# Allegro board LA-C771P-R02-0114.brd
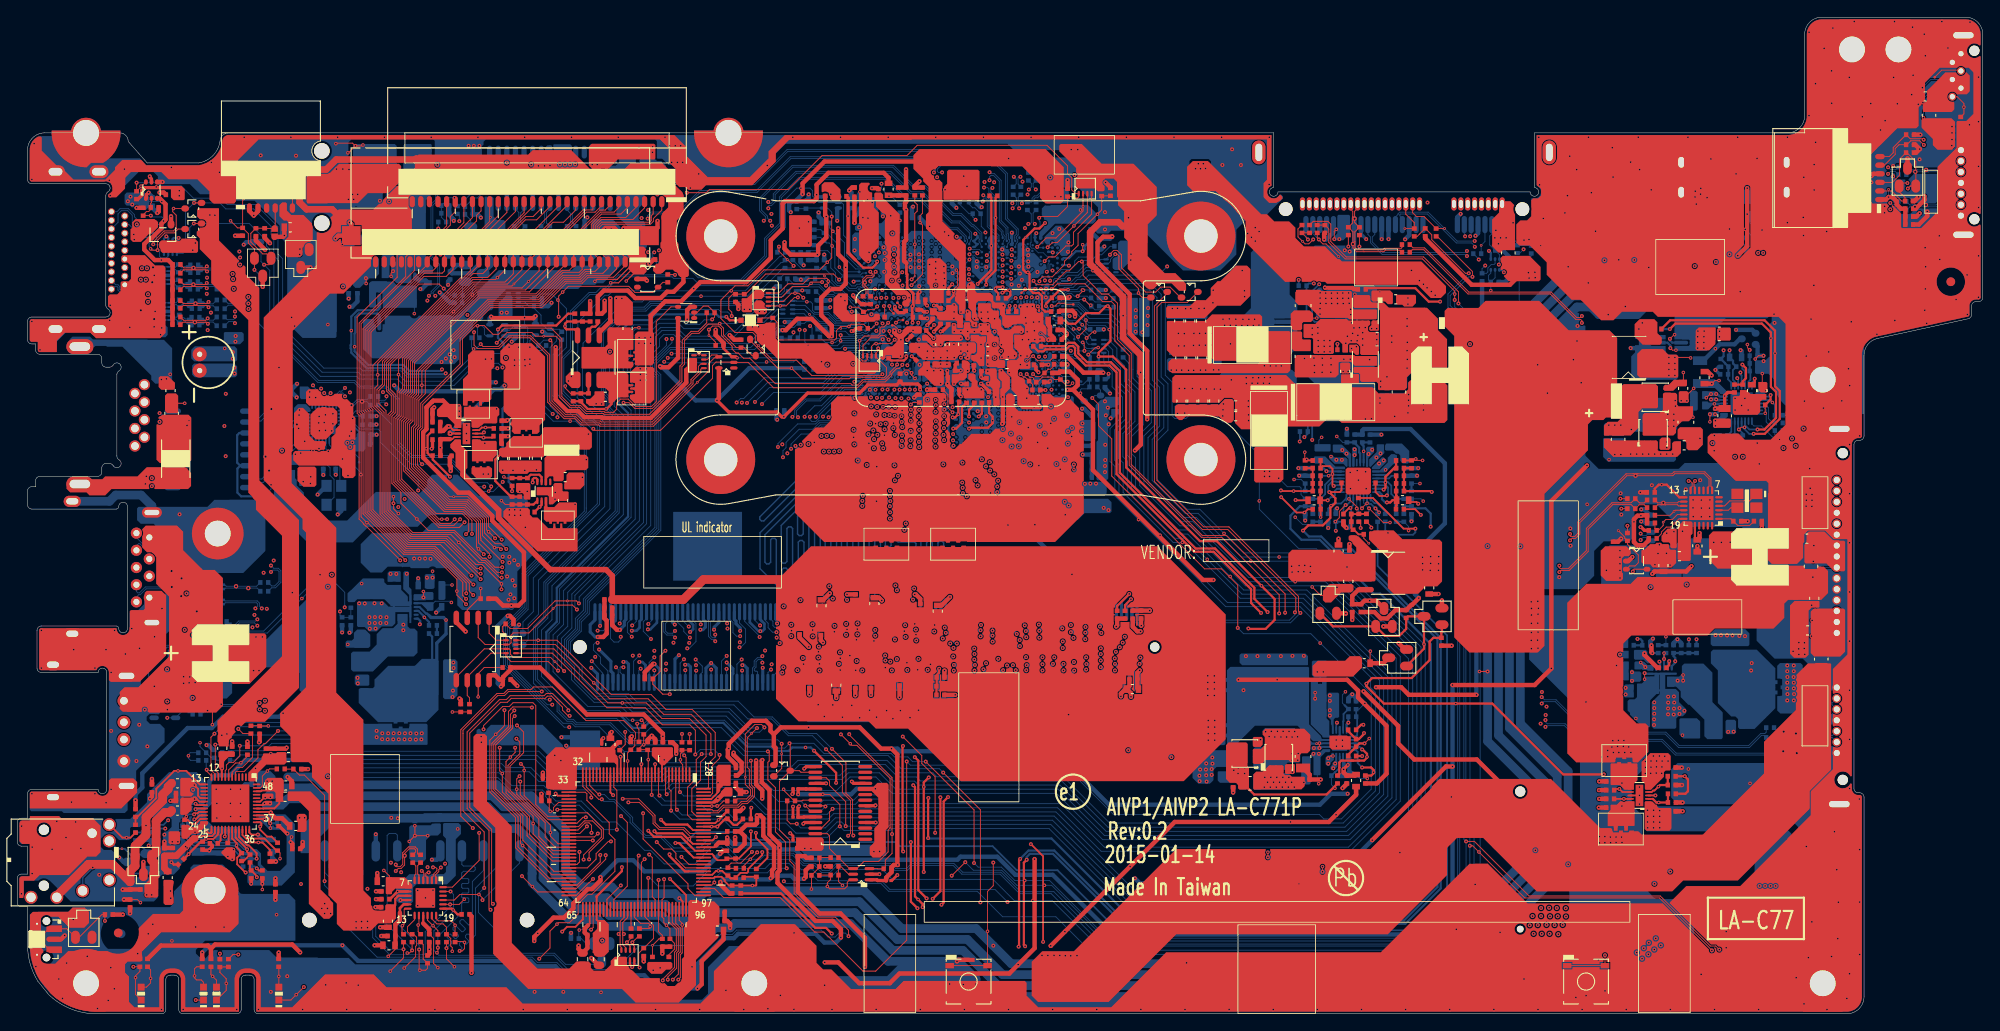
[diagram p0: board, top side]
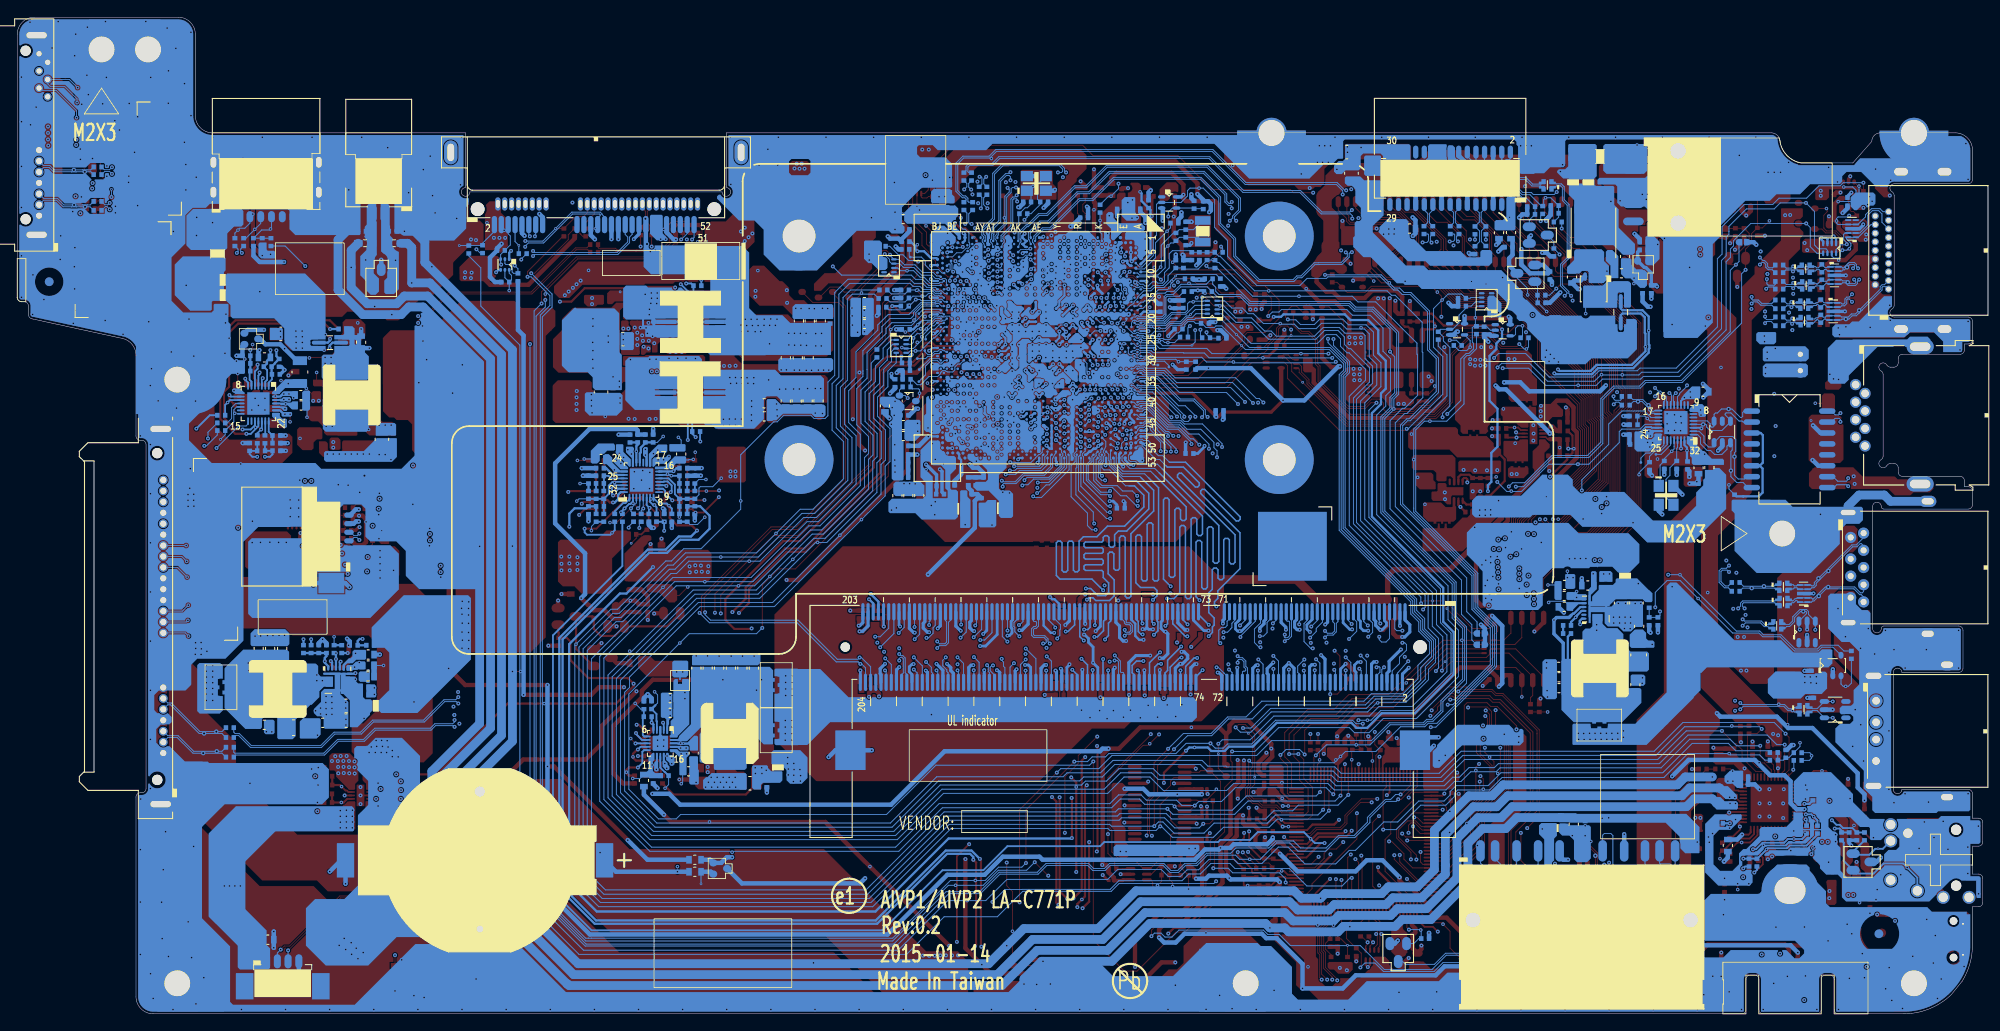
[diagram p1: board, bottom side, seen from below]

Outline 228.4 x 115.9 mm; copper layers: TOP, VCC, IN1, IN2, GND, BOTTOM. Coordinates in mm from the lower left corner of the outline.
Outline path: 0,22.25 arc(0.15,22.6) 0.5,22.75 1.2,22.75 1.2,25.6 arc(1.35,25.95) 1.7,26.1 9.4,26.1 arc(9.9,25.6) 10.4,26.1 10.4,39.7 arc(9.9,40.2) 9.4,39.7 2.8,39.7 arc(2.45,39.85) 2.3,40.2 2.3,44.6 arc(2.45,44.95) 2.8,45.1 11.5,45.1 arc(11.71,45.01) 11.8,44.8 arc(12.3,44.3) 12.8,44.8 12.8,59 arc(12.3,59.5) 11.8,59 arc(11.71,58.79) 11.5,58.7 1.7,58.7 arc(1.35,58.85) 1.2,59.2 1.2,60.8 arc(1.35,61.15) 1.7,61.3 2.14,61.3 2.14,62 arc(2.29,62.35) 2.64,62.5 9.33,62.5 arc(9.68,62.65) 9.83,63 9.83,63.5 arc(9.98,63.85) 10.33,64 10.71,64 arc(10.96,63.93) 11.15,63.75 arc(11.93,63.65) 11.83,64.43 arc(11.65,64.62) 11.58,64.87 11.58,74.33 arc(11.65,74.58) 11.83,74.77 arc(11.93,75.55) 11.15,75.45 arc(10.96,75.27) 10.71,75.2 10.33,75.2 arc(9.98,75.35) 9.83,75.7 9.83,76.2 arc(9.68,76.55) 9.33,76.7 2.64,76.7 arc(2.29,76.85) 2.14,77.2 2.14,77.9 1.7,77.9 arc(1.35,78.05) 1.2,78.4 1.2,80.53 arc(1.35,80.88) 1.7,81.03 10.3,81.03 arc(10.78,81.4) 10.55,81.96 arc(10.36,82.15) 10.3,82.4 10.3,95.16 arc(10.36,95.41) 10.55,95.6 arc(10.78,96.16) 10.3,96.53 1.7,96.53 arc(1.35,96.68) 1.2,97.03 1.2,100.45 arc(1.79,101.86) 3.2,102.45 6.5,102.45 arc(8,100.95) 9.5,102.45 11.9,102.45 arc(12.61,102.16) 12.9,101.45 15.1,98.95 21.1,98.95 arc(22.78,99.84) 23.58,101.56 arc(23.91,102.2) 24.57,102.45 81.15,102.45 arc(82.65,100.95) 84.15,102.45 146,102.45 146,96.08 arc(145.65,95.23) 146.5,95.58 175.8,95.58 arc(176.65,95.23) 176.3,96.08 176.3,102.45 205.7,102.45 arc(207.11,103.04) 207.7,104.45 207.7,113.9 arc(208.29,115.31) 209.7,115.9 226.4,115.9 arc(227.81,115.31) 228.4,113.9 228.4,83.32 arc(228.25,82.96) 227.9,82.82 227.6,82.82 arc(227.25,82.67) 227.1,82.32 227.1,81.32 arc(226.99,81.01) 226.71,80.83 216.18,78.54 arc(215.04,77.84) 214.6,76.59 214.6,67.2 arc(214.45,66.85) 214.1,66.7 213.93,66.7 arc(213.58,66.55) 213.43,66.2 213.43,26.2 arc(213.58,25.85) 213.93,25.7 214.1,25.7 arc(214.45,25.55) 214.6,25.2 214.6,2 arc(214.01,0.59) 212.6,0 28.03,0 arc(27.67,0.15) 27.52,0.5 27.52,4 arc(27.38,4.35) 27.03,4.5 26.52,4.5 arc(26.17,4.35) 26.03,4 26.03,0.5 arc(25.88,0.15) 25.52,0 19.27,0 arc(18.92,0.15) 18.77,0.5 18.77,4 arc(18.62,4.35) 18.27,4.5 17.77,4.5 arc(17.42,4.35) 17.27,4 17.27,0.5 arc(17.12,0.15) 16.77,0 9.2,0 arc(6.21,0.58) 3.66,2.23 2.4,3.79 arc(1.51,5.81) 1.2,8 1.2,12.45 0.5,12.45 arc(0.15,12.6) 0,12.95 0,15.75 arc(0.15,16.1) 0.5,16.25 1.2,16.25 1.2,19.5 0.5,19.5 arc(0.15,19.65) 0,20 0,22.25

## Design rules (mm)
net group 15: nets LAN_CLKREQ# SOC_I2C0_CLK
net group AUDIO-SPK: nets SPK_L1-_CONN SPK_L2+_CONN
net group DDI0_RCOMP: nets DDI0_RCOMPN DDI0_RCOMPP
net group DIFFPAIR8: nets ECAGND VCIN0_PH1
net group DIFFPAIR14: nets USB20_BT_R_N USB20_BT_R_P
net group HDMI_C_CLK: nets HDMI_C_CLK+ HDMI_C_CLK-
net group HDMI_C_TX0: nets HDMI_C_TX0+ HDMI_C_TX0-
net group HDMI_C_TX1: nets HDMI_C_TX1+ HDMI_C_TX1-
net group HDMI_C_TX2: nets HDMI_C_TX2+ HDMI_C_TX2-
net group HDMI_R_CK: nets HDMI_R_CK+ HDMI_R_CK-
net group HDMI_R_D0: nets HDMI_R_D0+ HDMI_R_D0-
net group HDMI_R_D1: nets HDMI_R_D1+ HDMI_R_D1-
net group HDMI_R_D2: nets HDMI_R_D2+ HDMI_R_D2-
net group ICLK_USB_TERM: nets ICLK_USB_TERMN ICLK_USB_TERMP
net group PCIE_COMP: nets PCIE_RCOMPN PCIE_RCOMPP
net group SATA_COMP: nets SATA_RCOMPN SATA_RCOMPP
net group SR: nets SRN SRP
net group U3RXD0: nets U3RXDN0 U3RXDP0
net group U3TXD0: nets U3TXDN0 U3TXDP0
net group USB20_0_L: nets USB20_N0_L USB20_P0_L
net group VCORE_VSNS: nets VCORE_GSNS VCORE_VSNS
net group 20: nets DDR_RCOMP0 DDR_RCOMP1 DDR_RCOMP2 DDR_TERMN0 DDR_TERMN1 GPIO_RCOMP HSIC_RCOMP ICLK_ICOMP ICLK_RCOMP LPC_RCOMP USB3_REXT0 USB_RCOMP VGFX_VSNS VSUM+ VSUM- VSUMG+ VSUMG- XTAL_25M_IN XTAL_25M_OUT XTLI XTLO
net group CARD-READER: nets SD_CD# SD_CMD SD_D0 SD_D1 SD_D2
net group CLK: nets CLK_PCIE_LAN CLK_PCIE_LAN# CLK_PCIE_WLAN CLK_PCIE_WLAN#
net group DDRA_ADD: nets DDR_A_BS0 DDR_A_BS1 DDR_A_BS2 DDR_A_CAS# DDR_A_MA0 DDR_A_MA1 DDR_A_MA2 DDR_A_MA3 DDR_A_MA4 DDR_A_MA5 DDR_A_MA6 DDR_A_MA7 DDR_A_MA8 DDR_A_MA9 DDR_A_MA10 DDR_A_MA11 DDR_A_MA12 DDR_A_MA13 DDR_A_MA14 DDR_A_MA15 DDR_A_RAS# DDR_A_WE#
net group DDRA_CTL: nets DDR_A_CKE0 DDR_A_CKE2 DDR_A_CS0# DDR_A_CS2#
net group DDRA_D0: nets DDR_A_D0 DDR_A_D1 DDR_A_D2 DDR_A_D3 DDR_A_D4 DDR_A_D5 DDR_A_D6 DDR_A_D7 DDR_A_DM0 DDR_A_DQS0 DDR_A_DQS#0
net group DDRA_D1: nets DDR_A_D8 DDR_A_D9 DDR_A_D10 DDR_A_D11 DDR_A_D12 DDR_A_D13 DDR_A_D14 DDR_A_D15 DDR_A_DM1 DDR_A_DQS1 DDR_A_DQS#1
net group DDRA_D2: nets DDR_A_D16 DDR_A_D17 DDR_A_D18 DDR_A_D19 DDR_A_D20 DDR_A_D21 DDR_A_D22 DDR_A_D23 DDR_A_DM2 DDR_A_DQS2 DDR_A_DQS#2
net group DDRA_D3: nets DDR_A_D24 DDR_A_D25 DDR_A_D26 DDR_A_D27 DDR_A_D28 DDR_A_D29 DDR_A_D30 DDR_A_D31 DDR_A_DM3 DDR_A_DQS3 DDR_A_DQS#3
net group DDRA_D4: nets DDR_A_D32 DDR_A_D33 DDR_A_D34 DDR_A_D35 DDR_A_D36 DDR_A_D37 DDR_A_D38 DDR_A_D39 DDR_A_DM4 DDR_A_DQS4 DDR_A_DQS#4
net group DDRA_D5: nets DDR_A_D40 DDR_A_D41 DDR_A_D42 DDR_A_D43 DDR_A_D44 DDR_A_D45 DDR_A_D46 DDR_A_D47 DDR_A_DM5 DDR_A_DQS5 DDR_A_DQS#5
net group DDRA_D6: nets DDR_A_D48 DDR_A_D49 DDR_A_D50 DDR_A_D51 DDR_A_D52 DDR_A_D53 DDR_A_D54 DDR_A_D55 DDR_A_DM6 DDR_A_DQS6 DDR_A_DQS#6
net group DDRA_D7: nets DDR_A_D56 DDR_A_D57 DDR_A_D58 DDR_A_D59 DDR_A_D60 DDR_A_D61 DDR_A_D62 DDR_A_D63 DDR_A_DM7 DDR_A_DQS7 DDR_A_DQS#7
net group DDRCLK: nets DDR_A_CLK0 DDR_A_CLK0# DDR_A_CLK2 DDR_A_CLK2#
net group EDP: nets EDP_AUXN EDP_AUXN_C EDP_AUXP EDP_AUXP_C EDP_TXN0 EDP_TXN0_C EDP_TXN1 EDP_TXN1_C EDP_TXP0 EDP_TXP0_C EDP_TXP1 EDP_TXP1_C
net group HDA: nets HDA_BIT_CLK HDA_BITCLK_AUDIO HDA_RCOMP HDA_RST# HDA_RST_AUDIO# HDA_SDIN0 HDA_SDOUT HDA_SDOUT_AUDIO HDA_SYNC HDA_SYNC_AUDIO
net group HDMI: nets HDMI_CLK+ HDMI_CLK- HDMI_DDCCLK HDMI_DDCDATA HDMI_TX0+ HDMI_TX0- HDMI_TX1+ HDMI_TX1- HDMI_TX2+ HDMI_TX2-
net group KB: nets KSI0 KSI1 KSI2 KSI3 KSI4 KSI5 KSI6 KSI7 KSO0 KSO1 KSO2 KSO3 KSO4 KSO5 KSO6 KSO7 KSO8 KSO9 KSO10 KSO11 KSO12 KSO13 KSO14 KSO15 KSO16
net group LAN: nets LAN_MDIN0 LAN_MDIN1 LAN_MDIP0 LAN_MDIP1 RJ45_RX1+ RJ45_RX1- RJ45_TX0+ RJ45_TX0-
net group LPC: nets LPC_AD0 LPC_AD1 LPC_AD2 LPC_AD3 LPC_CLK_0 LPC_CLK_1 LPC_CLK_EC LPC_FRAME#
net group PCIE: nets CLK_PCIE_CARD CLK_PCIE_CARD# PCIE_ATX_C_GRX_N0 PCIE_ATX_C_GRX_P0 PCIE_GTX_C_ARX_N0 PCIE_GTX_C_ARX_P0 PCIE_PRX_DTX_N0_C PCIE_PRX_DTX_N1 PCIE_PRX_DTX_N1_C PCIE_PRX_DTX_N3 PCIE_PRX_DTX_P0_C PCIE_PRX_DTX_P1 PCIE_PRX_DTX_P1_C PCIE_PRX_DTX_P3 PCIE_PTX_C_DRX_N1 PCIE_PTX_C_DRX_N3 PCIE_PTX_C_DRX_P1 PCIE_PTX_C_DRX_P3 PCIE_PTX_DRX_N1 PCIE_PTX_DRX_N2 PCIE_PTX_DRX_N3 PCIE_PTX_DRX_P1 PCIE_PTX_DRX_P2 PCIE_PTX_DRX_P3
net group RTC: nets ILB_RTC_EXTPAD ILB_RTC_X1 ILB_RTC_X2 RTC_RST# RTC_TEST#
net group SATA: nets SATA_PRX_C_DTX_N0 SATA_PRX_C_DTX_N1 SATA_PRX_C_DTX_P0 SATA_PRX_C_DTX_P1 SATA_PRX_DTX_N0 SATA_PRX_DTX_N1 SATA_PRX_DTX_P0 SATA_PRX_DTX_P1 SATA_PTX_C_DRX_N0 SATA_PTX_C_DRX_N1 SATA_PTX_C_DRX_P0 SATA_PTX_C_DRX_P1 SATA_PTX_DRX_N0 SATA_PTX_DRX_N1 SATA_PTX_DRX_P0 SATA_PTX_DRX_P1
net group SMBUS: nets DBG_UART_RXD DBG_UART_TXD EC_SMB_CK1 EC_SMB_CK2 EC_SMB_DA1 EC_SMB_DA2 PCU_SMB_CLK PCU_SMB_DATA TP_CLK TP_DATA
net group SPI: nets SOC_SPI_CLK SOC_SPI_CS0# SOC_SPI_MISO SOC_SPI_MOSI SPI_CLK SPI_CS0# SPI_HOLD# SPI_MISO SPI_MOSI SPI_WP#
net group SVID: nets VR_SVID_ALERT# VR_SVID_CLK VR_SVID_CLK_R VR_SVID_DATA VR_SVID_DATA_R
net group USB20: nets USB20_BT_N USB20_BT_P USB20_N0 USB20_N1 USB20_N1_L USB20_N2 USB20_N2_R USB20_N3 USB20_P0 USB20_P1 USB20_P1_L USB20_P2 USB20_P2_R USB20_P3 USB20_R_N3 USB20_R_P3 USB_HUB_BT_N3 USB_HUB_BT_P3 USB_HUB_N1 USB_HUB_P1
net group USB30: nets PCH_USB3_RX0_N PCH_USB3_RX0_P PCH_USB3_TX0_N PCH_USB3_TX0_N_C PCH_USB3_TX0_P PCH_USB3_TX0_P_C
net group XDP: nets XDP_H_PRDY# XDP_H_PREQ_BUF# XDP_H_TCK XDP_H_TDI XDP_H_TDO XDP_H_TMS XDP_H_TRST#
nets with their own width: min track width 0.508; nets +0.675VSP +1.05VS_SOC +1.8VALW +1.8VALWP +1.8VS +1.8VS_OUT +1.35V +1.35V_SOC +1.35VP +1.35VS +1.35VS_OUT +3VALW +3VALW_EC +3VALW_SOC +3VALWP +3VLP +3VS +3VS_OUT +3VS_SOC +5VALW +5VALWP +5VS +CHGRTC +DDR_SOC_VREF +EC_VCCA +MIC2-VREFO +RTCVCC +SOC_VCC +SOC_VNN +V18R GND
nets with their own width: min track width 1.016; nets +LAN_VDD
nets with their own width: min track width 1.524; nets +0.675VS +LCDVDD
nets with their own width: min track width 4.572; nets +5VS_OUT

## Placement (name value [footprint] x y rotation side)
C1  -  [C_0402]  219.4 91.79 0 top
C2  -  [C_0603]  32.44 91.46 180 top
C3  -  [C_0402]  219.48 100.15 0 top
C4  -  [C_0402]  219.37 94.52 0 top
C5  -  [C_0402]  219.49 101.07 0 top
C6  -  [C_0402]  219.49 102.24 0 top
C9  -  [C_0402]  14.26 5.47 90 top
C10  -  [C_0402]  27.74 91.36 270 top
C11  -  [C_0402]  26.2 91.4 270 top
C12  -  [C_0603]  199.98 8.62 180 bottom
CA1  -  [C_0402]  28.92 29.92 90 top
CA2  -  [C_0402]  29.93 29.92 90 top
CA3  -  [C_0402]  24.97 30.15 90 top
CA4  -  [C_0603]  31.91 26.55 180 top
CA5  -  [C_0402]  28.18 27.57 180 bottom
CA6  -  [C_0402]  28.2 26.68 180 bottom
CA7  -  [C_0402]  17.1 18.34 90 top
CA8  -  [C_0402]  18.07 18.37 90 top
CA9  -  [C_0402]  30.39 22.74 270 top
CA10  -  [C_0402]  28.17 33.48 270 top
CA11  -  [C_0402]  15.23 14.46 180 top
CA12  -  [C_0402]  26.75 31.04 270 top
CA13  -  [C_0402]  31.12 22.16 180 bottom
CA14  -  [C_0402]  13.11 15.35 270 top
CA15  -  [C_0402]  30.26 18.98 90 top
CA16  -  [C_0402]  21.55 19.11 90 top
CA17  -  [C_0402]  15.53 21.09 270 bottom
CA18  -  [C_0603]  29.62 18.87 90 bottom
CA19  -  [C_0402]  14.64 21.09 270 bottom
CA20  -  [C_0402]  23.3 19.82 180 top
CA21  -  [C_0402]  19.74 24.82 90 bottom
CA22  -  [C_0402]  29.37 17.71 90 top
CA23  -  [C_0402]  20.48 20.96 90 bottom
CA24  -  [C_0402]  19.21 20.96 90 bottom
CA25  -  [C_0402]  18.58 20.79 0 top
CA28  -  [C_0402]  187.88 91.01 0 bottom
CA29  -  [C_0402]  185.21 91.01 180 bottom
CA30  -  [C_0402]  24.73 29.5 180 bottom
CA31  -  [C_0402]  21.05 29.47 0 bottom
CA32  -  [C_0402]  24.74 30.39 180 bottom
CB1  -  [C_0402]  66.26 8.26 0 top
CB2  -  [C_0402]  66.25 9.15 0 top
CB3  -  [C_0201]  61.66 27.31 180 top
CB4  -  [C_0201]  67.92 30.8 90 top
CB5  -  [C_0402]  81.29 10.8 0 top
CB6  -  [C_0402]  81.31 11.84 0 top
CB7  -  [C_0402]  82.5 19.82 0 top
CB8  -  [C_0402]  61.82 24.77 180 top
CB10  -  [C_0402]  73.26 31.61 270 top
CB11  -  [C_0603]  82.64 25.79 0 top
CB12  -  [C_0402]  90.84 80.3 180 bottom
CB13  -  [C_0402]  83.51 26.83 180 top
CB14  -  [C_0402]  74.14 31.57 270 top
CC1  -  [C_0402]  116.11 62.39 270 bottom
CC2  -  [C_0402]  57.94 79 90 bottom
CC3  -  [C_0402]  60.98 82.3 180 bottom
CC4  -  [C_0402]  60.98 83.21 180 bottom
CC5  -  [C_0402]  82.07 77.73 180 top
CC6  -  [C_0402]  118.4 96.91 90 bottom
CC7  -  [C_0402]  117.51 96.91 90 bottom
CC8  -  [C_0402]  118.4 93.48 90 bottom
CC9  -  [C_0402]  117.38 93.48 90 bottom
CC10  -  [C_0402]  116.62 95.26 90 bottom
CC11  -  [C_0402]  115.73 95.26 90 bottom
CC12  -  [C_0402]  110.59 94.41 0 bottom
CC13  -  [C_0402]  109.53 94.41 180 bottom
CC14  -  [C_0402]  98.84 79.71 180 top
CC15  -  [C_0402]  124.75 88.91 0 bottom
CC16  -  [C_0402]  83.47 83.7 270 top
CC17  -  [C_0402]  94.39 91.95 180 bottom
CC18  -  [C_0402]  92.61 91.19 90 bottom
CC19  -  [C_0402]  92.61 90.3 270 bottom
CC20  -  [C_0402]  104.82 71.1 90 top
CC21  -  [C_0402]  91.65 93.63 90 bottom
CC22  -  [C_0402]  56.42 38.87 0 top
CC23  -  [C_0402]  93.88 95.13 90 top
CC24  -  [C_0402]  91.03 88.57 270 bottom
CC25  -  [C_0402]  93.77 86.73 90 bottom
CC26  -  [C_0402]  51.53 36.02 270 top
CC27  -  [C_0402]  124.78 83.24 0 bottom
CC28  -  [C_0402]  124.78 84.18 0 bottom
CC29  -  [C_0402]  109.46 72.58 180 top
CC30  -  [C_0402]  121.57 61.38 0 bottom
CC31  -  [C_0402]  118.4 60.44 180 bottom
CC32  -  [C_0402]  116.37 59.06 90 bottom
CC33  -  [C_0402]  119.46 60.54 90 bottom
CC34  -  [C_0402]  125.76 66.05 180 bottom
CC35  -  [C_0402]  100.62 58.81 180 bottom
CC36  -  [C_0402]  91.73 65.16 0 bottom
CC37  -  [C_0603]  115.24 71.37 0 top
CC38  -  [C_0603]  119.41 71.42 180 top
CC39  -  [C_0603]  124.75 92.41 0 bottom
CC40  -  [C_0603]  109.59 83.55 0 top
CC41  -  [C_0402]  109.88 82.35 0 top
CC42  -  [C_0402]  108.18 80.19 90 top
CC43  -  [C_0402]  109.91 74.15 0 top
CC44  -  [C_0402]  110.09 75.67 180 top
CC45  -  [C_0402]  120.05 95.54 90 bottom
CC46  -  [C_0402]  108.99 73.88 90 top
CC47  -  [C_0402]  92.92 82.99 270 bottom
CC48  -  [C_0402]  104.88 92.57 180 bottom
CC49  -  [C_0402]  93.86 82.97 270 bottom
CC50  -  [C_0402]  97.32 96.09 0 top
CC51  -  [C_0402]  106.38 81.76 270 top
CC52  -  [C_0402]  97.9 93.61 0 bottom
CC53  -  [C_0402]  100.59 93.58 180 bottom
CC54  -  [C_0402]  112.81 82.3 90 top
CC55  -  [C_0402]  106.44 83.02 180 top
CC56  -  [C_0402]  115.86 79.51 90 top
CC57  -  [C_0402]  114.08 80.07 0 top
CC58  -  [C_0402]  105.64 79.47 180 top
CC59  -  [C_0402]  111.23 73.24 180 top
CC60  -  [C_0402]  116.24 77.73 180 top
CC61  -  [C_0402]  95.59 82.56 270 bottom
CC62  -  [C_0402]  119.06 75.47 180 top
CC63  -  [C_0402]  112.05 75.67 270 top
CC64  -  [C_0402]  107.29 81.15 270 top
CC65  -  [C_0402]  108.15 74 180 top
CC66  -  [C_0402]  111.92 83.19 270 top
CC67  -  [C_0402]  89.14 70.16 180 bottom
CC68  -  [C_0402]  108.21 82.05 180 top
CC69  -  [C_0402]  124.87 63.25 0 bottom
CC70  -  [C_0402]  124.87 64.14 0 bottom
CC71  -  [C_0402]  124.87 65.03 0 bottom
CC72  -  [C_0603]  124.85 59.55 90 bottom
CC73  -  [C_0603]  123.58 59.55 90 bottom
CC74  -  [C_0402]  124.87 62.37 0 bottom
CC75  -  [C_0603]  126.12 59.55 90 bottom
CC76  -  [C_0402]  103.23 81.74 90 top
CC77  -  [C_0402]  113.55 73.9 180 top
CC78  -  [C_0402]  125.64 91.22 180 bottom
CC79  -  [C_0402]  102.39 95.18 90 top
CC80  -  [C_0402]  109.56 80.94 0 top
CC81  -  [C_0402]  104.07 81.02 0 top
CC82  -  [C_0402]  113.76 82.35 270 top
CC83  -  [C_0402]  103.28 95.18 90 top
CC84  -  [C_0402]  113.84 72.34 180 top
CC85  -  [C_0402]  104.66 82.8 270 top
CC86  -  [C_0402]  100.07 95.91 270 top
CC87  -  [C_0402]  125.76 69.6 180 bottom
CC88  -  [C_0402]  126.4 73.8 270 bottom
CC89  -  [C_0402]  120 79.53 0 top
CC90  -  [C_0402]  111.16 76.32 270 top
CC91  -  [C_0402]  120.46 78.41 0 top
CC92  -  [C_0402]  116.16 78.65 180 top
CC93  -  [C_0402]  98.2 95 180 top
CC94  -  [C_0402]  107.57 72.59 180 top
CC95  -  [C_0402]  122.05 95.04 90 top
CD1  -  [C_0402]  68.22 47.21 0 top
CD2  -  [C_0402]  73.85 38.95 180 top
CD3  -  [C_0402]  106.84 39.12 0 top
CD4  -  [C_0603]  93.45 46.74 90 top
CD5  -  [C_0603]  95.17 38.93 270 top
CD6  -  [C_0603]  99.6 47 90 top
CD7  -  [C_0603]  106.97 46.11 90 top
CD8  -  [C_0402]  93.38 44.96 270 top
CD9  -  [C_0402]  97.42 47.86 90 top
CD10  -  [C_0402]  102.52 39.1 270 top
CD11  -  [C_0402]  104.93 46.74 90 top
CD12  -  [C_0402]  92.05 38.8 270 top
CD13  -  [C_0402]  99.21 38.8 270 top
CD14  -  [C_0402]  97.39 38.8 270 top
CD15  -  [C_0402]  90.91 45.04 270 top
CD16  -  [C_0603]  130.29 37.76 180 top
CD17  -  [C_0402]  130.16 38.93 180 top
CD18  -  [C_0402]  130.59 45.98 90 top
CD19  -  [C_0402]  128.73 46.86 270 top
CL1  -  [C_0402]  33.04 61.67 180 bottom
CL2  -  [C_0402]  33.54 69.4 0 top
CL3  -  [C_0402]  33.56 68.18 0 top
CL4  -  [C_0402]  40.07 66.23 0 bottom
CL5  -  [C_0402]  35.57 66.3 90 top
CL6  -  [C_0402]  40.14 67.35 0 bottom
CL7  -  [C_0402]  35.62 71.23 270 top
CL8  -  [C_0402]  33 64.25 270 top
CL9  -  [C_0603]  33.23 72.35 180 bottom
CL10  -  [C_0603]  33.04 64.21 270 bottom
CL11  -  [C_0402]  41.03 71.8 0 bottom
CL12  -  [C_0402]  41.03 70.78 0 bottom
CL13  -  [C_0402]  37.01 63.38 90 bottom
CL14  -  [C_0603]  17.81 71.76 90 top
CL15  -  [C_0402]  28.84 60.37 270 bottom
CL16  -  [C_0402]  35.57 63.38 90 bottom
CLRP1  -  [SHORTPADS]  58.33 44.23 180 bottom
CLRP2  -  [SHORTPADS]  58.33 42.92 180 bottom
CM1  -  [C_0402]  173.64 90.56 0 top
CO1  -  [C_0402]  203.23 33.28 0 bottom
CO2  -  [C_0402]  203.23 29.85 0 bottom
CO3  -  [C_0402]  203.23 30.99 0 bottom
CO4  -  [C_0402]  218.6 93.44 0 bottom
CO5  -  [C_0402]  218.6 94.48 0 bottom
CO6  -  [C_0402]  218.6 97.59 0 bottom
CO7  -  [C_0402]  203.23 32.14 0 bottom
CO8  -  [C_0402]  218.6 98.48 0 bottom
CO9  -  [C_0603]  222.41 106.69 180 top
CO10  -  [C_0603]  208.82 49.03 270 top
CO11  -  [C_0402]  207.68 48.44 270 top
CO12  -  [C_0402]  206.66 48.44 270 top
CO13  -  [C_0603]  208.76 44.59 180 top
CO14  -  [C_0603]  208.67 55.25 180 top
CQ1  -  [C_0402]  192.71 23.56 180 top
CQ2  -  [C_0402]  184.64 25 0 top
CQ3  -  [C_0402]  184.64 23.98 0 top
CQ4  -  [C_0402]  191.82 24.58 0 top
CQ5  -  [C_0402]  184.65 27.03 0 top
CQ6  -  [C_0402]  184.65 26.01 0 top
CQ7  -  [C_0402]  192.71 26.61 180 top
CQ8  -  [C_0402]  192.71 28.64 180 top
CQ9  -  [C_0402]  48.26 69.82 0 top
CQ10  -  [C_0402]  56.29 68.08 180 top
CQ11  -  [C_0402]  56.29 68.97 180 top
CQ12  -  [C_0402]  48.26 68.81 0 top
CQ13  -  [C_0402]  56.29 66.3 180 top
CQ14  -  [C_0402]  56.26 67.18 180 top
CQ15  -  [C_0402]  48.26 66.77 0 top
CQ16  -  [C_0402]  50.48 64.88 0 top
CQ17  -  [C_0603]  164.07 48.82 90 top
CQ18  -  [C_0603]  153.53 54.53 270 top
CQ19  -  [C_0402]  154.8 53.9 270 top
CQ20  -  [C_0402]  155.13 47.64 270 top
CR1  -  [C_0603]  43.24 15.42 180 top
CR2  -  [C_0402]  43.24 14.25 180 top
CR3  -  [C_0603]  43.9 7.97 180 top
CR4  -  [C_0402]  43.95 9.05 180 top
CR5  -  [C_0603]  43.08 10.06 90 top
CR6  -  [C_0402]  42.3 12.4 0 top
CR7  -  [C_0402]  46.87 18.49 270 top
CR8  -  [C_0402]  45.96 18.49 270 top
CR9  -  [C_0402]  47.68 5.88 90 top
CR10  -  [C_0402]  47.88 8.34 90 top
CR11  -  [C_0603]  47.53 21.34 90 bottom
CR12  -  [C_0402]  46.2 21.5 90 bottom
CS1  -  [C_0402]  28.25 50.16 0 bottom
CS2  -  [C_0402]  28.25 49.14 0 bottom
CS3  -  [C_0402]  19.92 39.89 90 bottom
CS4  -  [C_MP6VLPS220MC4R2]  20.83 41.94 180 top
CS5  -  [C_0402]  19.64 37.66 270 bottom
CS6  -  [C_0402]  185.45 53.98 90 top
CS7  -  [C_0402]  193.33 54.49 180 top
CS8  -  [C_0402]  193.33 55.38 180 top
CS9  -  [C_0603]  195.23 55.13 270 top
CS10  -  [C_0603]  191.3 52.84 270 top
CS11  -  [C_0402]  199.42 57.29 0 top
CS12  -  [C_0402]  189.59 56.22 0 top
CS13  -  [C_0402]  191.55 55.25 270 top
CS14  -  [C_MP6VLPS220MC4R2]  199.7 53.15 180 top
CW1  -  [C_0201]  90.73 20.2 180 top
CW2  -  [C_0201]  90.73 22.87 180 top
CW3  -  [C_0201]  90.74 26.17 180 top
CW4  -  [C_0201]  100.96 15.5 0 top
CX1  -  [C_0603]  67.32 91.32 180 bottom
CX2  -  [C_0402]  75.04 87.72 180 top
CX3  -  [C_0402]  57.74 90.66 90 bottom
CX4  -  [C_0402]  59.01 90.66 90 bottom
CX5  -  [C_0402]  60.86 90.68 90 bottom
CX6  -  [C_0402]  61.88 90.68 90 bottom
CX7  -  [C_0402]  63.91 90.68 90 bottom
CX8  -  [C_0402]  64.93 90.68 90 bottom
CX9  -  [C_0805]  73.06 100.21 0 bottom
CX10  -  [C_0402]  50.3 85.4 90 bottom
CX11  -  [C_0402]  54.64 89.16 0 bottom
CX12  -  [C_0603]  56.22 91.55 270 bottom
CX13  -  [C_0402]  51.72 82.69 180 bottom
CX14  -  [C_0402]  50.2 93.1 180 bottom
CX15  -  [C_0402]  52.94 93.86 180 bottom
CY1  -  [C_0402]  23.19 84.28 0 bottom
CY2  -  [C_0402]  23.19 85.17 0 bottom
CY3  -  [C_0402]  23.18 81.03 0 bottom
CY4  -  [C_0402]  23.18 80.02 0 bottom
CY5  -  [C_0402]  23.19 83.01 0 bottom
CY6  -  [C_0402]  23.19 82 0 bottom
CY7  -  [C_0402]  23.2 86.19 0 bottom
CY8  -  [C_0402]  23.2 87.08 0 bottom
CY9  -  [C_0402]  14.81 94.92 0 bottom
CY10  -  [C_0402]  14.64 93.73 270 top
CY11  -  [C_0402]  15.73 93.96 180 bottom
CY12  -  [C_0402]  18.19 95.26 180 top
D1  -  [YSLC05CH_SOT23-3]  219.65 98.34 180 top
D2  -  [PSOT24C_SOT23-3]  28.53 85.78 0 top
D3  -  [PSOT24C_SOT23-3]  32.95 86.8 0 top
D4  -  [L03ESDL5V0CC3-2_SOT23-3]  7.73 10.98 180 top
DA3  -  [L03ESDL5V0CC3-2_SOT23-3]  14.66 16.2 0 top
DA4  -  [L03ESDL5V0CC3-2_SOT23-3]  186.1 86.57 0 bottom
DA5  -  [L03ESDL5V0CC3-2_SOT23-3]  12.99 17.66 90 bottom
DC1  -  [RB751V40_SC76-2]  84.11 80.65 0 top
DL1  -  [BS4200N-C-LV_SMB-F2]  18.42 62.35 90 top
DL2  -  [AZC099-04SPR7G_SOT23-6]  31.22 66.42 180 bottom
DS1  -  [L05ESDL5V0NA-4_SLP2510P8-10-9]  20.38 47.87 270 bottom
DS2  -  [AZC099-04SPR7G_SOT23-6]  21.37 43.15 180 bottom
DS3  -  [AZC099-04SPR7G_SOT23-6]  15.91 34.42 90 bottom
DY1  -  [L05ESDL5V0NA-4_SLP2510P8-10-9]  14.76 90.3 270 bottom
DY2  -  [L05ESDL5V0NA-4_SLP2510P8-10-9]  17.68 86.87 90 bottom
DY3  -  [L05ESDL5V0NA-4_SLP2510P8-10-9]  17.81 82.69 90 bottom
FD1  -  [FIDUCIAL_C40M80]  11.74 9.41 0 top
FD2  -  [FIDUCIAL_C40M80]  224.68 85.14 180 bottom
FD3  -  [FIDUCIAL_C40M80]  12.07 9.31 180 bottom
FD4  -  [FIDUCIAL_C40M80]  224.68 85.14 0 top
H1  -  [H_3P0]  213.2 112.15 0 top
H2  -  [H_3P0]  218.6 112.15 0 top
H3  -  [H_3P0]  209.8 73.75 0 top
H4  -  [H_3P0]  209.8 3.55 0 top
H5  -  [H_3P0]  85.65 3.55 0 top
H6  -  [H_3P1X3P6]  22.4 14.35 90 top
H7  -  [H_3P0]  8 3.55 0 top
H8  -  [H_3P0]  23.3 55.85 0 top
H9  -  [H_3P8]  137.55 90.45 0 top
H10  -  [H_3P8]  137.55 64.45 0 top
H11  -  [H_3P8]  81.75 64.45 0 top
H12  -  [H_3P8]  81.75 90.45 0 top
H13  -  [H_3P0]  8 102.45 0 top
H14  -  [H_3P0]  82.65 102.45 0 top
J1  -  [SHORTPADS]  27.85 89.74 0 bottom
J2  -  [SHORTPADS]  29.91 90.84 90 top
JBATT1  -  [SUYIN_125022HB008M200ZL_8P-T]  203.85 92.7 0 bottom
JDCIN1  -  [ACES_50299-00501-003_5P]  40.6 100.15 270 bottom
JDIMM1  -  [LCN_DAN06-K4406-0102_204P]  67.13 46.75 0 bottom
JEDP1  -  [ACES_87242-3001-09_30P]  54.9 94.11 0 bottom
JHDD1  -  [SDAN_603015-022041_22P-T]  211.43 30.32 270 bottom
JHDMI1  -  [LOTES_AHDM0006-P004A_19P]  10.95 84.28 90 bottom
JHP1  -  [SANTA_311108-1_7P]  10.7 20.1 90 top
JKB1  -  [ACES_88514-3001_30P]  70.65 87.45 180 top
JKB2  -  [ACES_88514-3001_30P]  74.9 94.45 180 top
JLAN1  -  [SANTA_130452-S_8P]  14.78 73.17 90 bottom
JODD1  -  [SANTA_201304-1_13P]  225.86 92.82 270 bottom
JP1  -  [ACES_85205-0400_4P]  199.42 6.1 180 bottom
JPWRB1  -  [ACES_88058-060N_6P]  26.98 93.7 180 top
JRTC1  -  [LOTES_AAA-BAT-054-K01_2P]  160.15 17.85 180 bottom
JSB1  -  [ACES_88058-060N_6P]  189.85 53 270 bottom
JSD1  -  [FOX_WK21921-R93-9H_11P]  54.17 18.95 180 bottom
JSPK1  -  [E-T_3806K-F02N-03R_2P]  185.77 93.1 0 bottom
JTP1  -  [ACES_88058-060N_6P]  216.45 94.69 270 top
JUSB1  -  [SINGA_2UB4039-200011F_9P]  15.35 55.4 90 bottom
JUSB2  -  [SDAN_608050-004041_4P]  12.4 36.4 90 bottom
JWLAN1  -  [BELLW_80019-1021_52P]  172.95 91.78 0 bottom
L1  -  [TDK_MPZ2012S101AT000_2P]  118.3 58.73 0 bottom
L2  -  [TDK_MPZ2012S101AT000_2P]  115.2 58.78 180 bottom
L3  -  [L_FBM-11-160808_2P]  65.69 5.65 90 top
L4  -  [L_FBM-11-160808_2P]  67.6 5.65 90 top
LA1  -  [CHENG_MBK1608121YZF_2P]  183.81 89.61 0 bottom
LA2  -  [CHENG_MBK1608121YZF_2P]  188.77 89.61 180 bottom
LED1  -  [LED_19-217-T1D-DP1Q2QY-3T_2P]  14.4 1.6 90 top
LED2  -  [LED_19-213A-T1D-CP2Q2HY-3T_2P]  21.65 1.6 90 top
LED3  -  [LED_19-217-T1D-DP1Q2QY-3T_2P]  23.15 1.6 90 top
LED4  -  [LED_19-217-T1D-DP1Q2QY-3T_2P]  30.4 1.6 90 top
LR1  -  [MURAT_BLM18PG300SN1D_2P]  48.8 21.6 0 bottom
LS1  -  [INPAQ_HCM1012GH900BP_4P]  23.8 49.9 180 bottom
LS2  -  [INPAQ_HCM1012GH900BP_4P]  23.78 48.14 180 bottom
LS3  -  [INPAQ_HCM1012GH900BP_4P]  24.57 45.36 180 bottom
LS4  -  [INPAQ_HCM1012GH900BP_4P]  21.39 35.61 180 bottom
LX1  -  [INPAQ_HCM1012GH900BP_4P]  49.98 96.12 0 bottom
LY1  -  [INPAQ_HCM1012GH900BP_4P]  21.19 86.9 180 bottom
LY2  -  [INPAQ_HCM1012GH900BP_4P]  21.37 82.72 180 bottom
LY3  -  [INPAQ_HCM1012GH900BP_4P]  21.15 84.96 180 bottom
LY4  -  [INPAQ_HCM1012GH900BP_4P]  21.33 80.81 180 bottom
MIC1  -  [MIC_WM-64PCY_2P]  21.2 76.7 90 top
NOREF  -  []  137.55 64.45 0 top
NOREF#2  -  []  8 102.45 0 top
NOREF#3  -  []  81.75 64.45 0 top
NOREF#4  -  []  209.8 73.75 90 top
NOREF#5  -  []  22.4 14.35 0 top
NOREF#6  -  []  209.8 3.55 90 top
NOREF#7  -  []  137.55 90.45 0 top
NOREF#8  -  []  8.55 143.76 0 top
NOREF#9  -  []  8 102.45 0 top
NOREF#10  -  []  218.6 112.15 0 top
NOREF#11  -  []  123.99 26.64 0 top
NOREF#12  -  []  130.46 52.97 0 top
NOREF#13  -  []  197.46 9.95 0 top
NOREF#14  -  []  213.2 112.15 0 top
NOREF#15  -  []  23.3 55.85 0 top
NOREF#16  -  []  8 3.55 0 top
NOREF#17  -  []  82.65 102.45 0 top
NOREF#18  -  []  72.8 55.51 0 top
NOREF#19  -  []  85.65 3.55 0 top
NOREF#20  -  []  81.75 90.45 0 top
NOREF#21  -  []  91.09 -42.54 0 top
NOREF#22  -  []  82.65 102.45 0 top
NOREF#23  -  []  80.22 54.37 180 bottom
NOREF#24  -  []  205.35 54.01 90 bottom
NOREF#25  -  []  131.73 13.72 180 bottom
NOREF#26  -  []  124.75 33.03 180 bottom
NOREF#27  -  []  126.02 21.47 180 bottom
NOREF#28  -  []  216.1 86.55 180 bottom
NOREF#29  -  []  211.89 99.46 90 bottom
PC100  -  [C_0402]  47.91 100.47 0 bottom
PC101  -  [C_0402]  47.91 99.45 0 bottom
PC102  -  [C_0402]  43.34 95.89 90 bottom
PC103  -  [C_0402]  44.36 95.89 90 bottom
PC104  -  [C_0402]  206.15 82.18 180 bottom
PC105  -  [C_0402]  203.23 82.18 0 bottom
PC200  -  [C_0603]  41.56 88.78 270 bottom
PC201  -  [C_0603]  188.44 78.81 270 bottom
PC202  -  [C_0603]  47.73 86.39 270 bottom
PC203  -  [C_0402]  184.69 67.52 270 top
PC204  -  [C_0402]  184.69 67.52 270 bottom
PC205  -  [C_0805]  186.02 67.66 270 top
PC206  -  [C_0805]  186.02 67.66 270 bottom
PC207  -  [C_0603]  200.38 76.34 180 bottom
PC208  -  [C_0402]  199.75 75.26 180 bottom
PC209  -  [C_0402]  197.96 76.16 270 bottom
PC210  -  [C_0402]  198.8 74.37 180 bottom
PC211  -  [C_0603]  196.06 74.68 270 top
PC212  -  [C_0402]  201.32 75.64 0 bottom
PC213  -  [C_0805]  198.41 70.39 270 top
PC214  -  [C_0603]  194.72 71.95 0 bottom
PC215  -  [C_0603]  201.58 71.76 90 top
PC216  -  [C_0603]  202.79 71.76 90 top
PC217  -  [C_0402]  202.2 70.81 0 top
PC218  -  [C_0805]  196.92 79.07 0 bottom
PC219  -  [C_0603]  194.41 66.11 180 top
PC220  -  [C_0805]  196.92 79.07 0 top
PC221  -  [C_0402]  200.52 65.48 180 bottom
PC222  -  [C_0402]  201.39 65.46 90 bottom
PC223  -  [C_0402]  198.74 65.48 180 bottom
PC301  -  [C_0402]  188.48 37.11 180 bottom
PC302  -  [C_0402]  191.58 41.96 90 bottom
PC303  -  [C_0402]  188.48 37.99 180 bottom
PC304  -  [C_0603]  186.93 39.24 0 bottom
PC305  -  [C_0805]  189.33 35.81 0 bottom
PC306  -  [C_0805]  189.33 34.1 0 bottom
PC307  -  [C_0603]  200.34 41.78 90 bottom
PC308  -  [C_0603]  197.61 41.78 90 bottom
PC309  -  [C_0603]  200.41 33.61 180 bottom
PC310  -  [C_0603]  199.01 41.78 90 bottom
PC311  -  [C_0603]  188.33 41.78 180 bottom
PC312  -  [C_0603]  193.61 33.84 180 bottom
PC313  -  [C_0402]  192.47 41.96 90 bottom
PC314  -  [C_0805]  42.02 48.63 270 bottom
PC315  -  [C_0805]  40.24 48.63 270 bottom
PC316  -  [C_0402]  43.36 49.6 90 bottom
PC317  -  [C_0402]  47.85 45.17 0 bottom
PC318  -  [C_0603]  49.32 49.87 180 bottom
PC319  -  [C_0402]  44.24 49.6 90 bottom
PC320  -  [C_0603]  47.93 47.33 0 bottom
PC321  -  [C_0603]  48.54 39.14 0 bottom
PC322  -  [C_0603]  48.54 37.87 0 bottom
PC323  -  [C_0603]  40.37 37.55 90 bottom
PC324  -  [C_0603]  48.56 40.35 0 bottom
PC325  -  [C_0603]  45.2 49.81 0 bottom
PC326  -  [C_0603]  39.93 44.35 90 bottom
PC327  -  [C_0402]  38.77 46.11 270 bottom
PC401  -  [C_0402]  141.29 27.26 270 bottom
PC402  -  [C_0402]  141.29 27.26 270 top
PC403  -  [C_0805]  142.41 26.8 0 bottom
PC404  -  [C_0805]  142.41 26.8 0 top
PC405  -  [C_0603]  149.67 28.2 0 bottom
PC406  -  [C_0603]  151.83 35 0 bottom
PC407  -  [C_0603]  151.83 36.71 0 bottom
PC408  -  [C_0402]  154.5 26.79 90 top
PC409  -  [C_0603]  146.84 39.49 90 bottom
PC410  -  [C_0603]  144.13 39.49 90 bottom
PC411  -  [C_0603]  149.48 39.49 90 bottom
PC412  -  [C_0603]  148.17 39.49 90 bottom
PC413  -  [C_0603]  145.47 39.49 90 bottom
PC414  -  [C_0603]  142.8 39.49 90 bottom
PC415  -  [C_0402]  154.69 35.44 90 bottom
PC416  -  [C_0402]  154.5 27.71 270 bottom
PC417  -  [C_0402]  150.18 27.25 180 top
PC418  -  [C_0402]  155.58 31.06 180 top
PC419  -  [C_0402]  155.58 31.95 180 top
PC501  -  [C_0402]  59.28 62.3 270 top
PC502  -  [C_0603]  63.43 58.98 90 top
PC503  -  [C_0402]  57.5 60.15 270 top
PC504  -  [C_0603]  57.71 65.31 270 top
PC505  -  [C_0603]  56.44 65.31 270 top
PC506  -  [C_0603]  60.39 65.33 270 top
PC507  -  [C_0603]  59 65.33 270 top
PC508  -  [C_0402]  63.87 61.34 180 top
PC601  -  [C_0402]  68.92 80.55 0 top
PC602  -  [C_0603]  70.92 79 90 top
PC603  -  [C_0402]  65.68 80.51 90 top
PC604  -  [C_0402]  65.49 71.24 90 top
PC605  -  [C_0603]  69.05 71.76 180 top
PC701  -  [C_6P3X4P5]  165.34 77.05 270 top
PC702  -  [C_0603]  130.67 82.76 180 bottom
PC703  -  [C_0603]  130.67 80.22 180 bottom
PC704  -  [C_0603]  130.67 81.49 180 bottom
PC705  -  [C_0402]  162.02 59.03 270 bottom
PC706  -  [C_0402]  112.28 78.46 0 top
PC707  -  [C_0402]  109.56 80.07 0 top
PC708  -  [C_0402]  133.95 81.17 270 bottom
PC709  -  [C_0402]  156.92 61.74 0 top
PC710  -  [C_0402]  133.95 81.17 270 top
PC711  -  [C_0402]  134.27 76.01 90 bottom
PC712  -  [C_0402]  135.29 76.01 90 bottom
PC713  -  [C_0402]  160.24 60.8 270 bottom
PC714  -  [C_0402]  160.24 58.14 270 bottom
PC715  -  [C_0603]  135.03 81.29 270 top
PC716  -  [C_0402]  161.14 64.35 180 top
PC717  -  [C_0402]  113.42 74.76 90 top
PC718  -  [C_0603]  135.16 75.57 90 top
PC719  -  [C_0402]  161.13 60.8 270 bottom
PC720  -  [C_0402]  159.16 72.78 270 bottom
PC721  -  [C_0805]  160.56 73.16 270 top
PC722  -  [C_0805]  158.87 78.47 180 bottom
PC723  -  [C_0603]  136.43 75.57 90 bottom
PC724  -  [C_0402]  162.02 61.67 90 bottom
PC725  -  [C_0402]  158.3 65.85 0 bottom
PC726  -  [C_0402]  161.14 61.68 180 top
PC727  -  [C_0402]  161.14 62.57 180 top
PC731  -  [C_0402]  148.9 79.87 0 top
PC732  -  [C_0603]  137.7 75.57 90 top
PC733  -  [C_0402]  157.19 67.36 270 bottom
PC734  -  [C_0603]  136.43 75.57 90 top
PC735  -  [C_0603]  137.57 81.29 270 bottom
PC736  -  [C_0603]  135.03 81.29 270 bottom
PC738  -  [C_0402]  154.51 66.45 90 bottom
PC739  -  [C_0805]  158.87 78.47 180 top
PC740  -  [C_0402]  159.16 72.78 270 top
PC741  -  [C_0805]  160.56 73.16 270 bottom
PC742  -  [C_0603]  139.1 75.57 90 bottom
PC743  -  [C_0603]  137.7 75.57 90 bottom
PC744  -  [C_0402]  155 58.14 270 bottom
PC745  -  [C_0603]  136.3 81.29 270 bottom
PC746  -  [C_0603]  115.73 75.57 180 top
PC747  -  [C_0603]  112.07 77.05 0 top
PC748  -  [C_0603]  136.3 81.29 270 top
PC749  -  [C_0603]  137.57 81.29 270 top
PC750  -  [C_0402]  155.02 57.23 180 top
PC751  -  [C_0402]  153.19 65.86 180 bottom
PC752  -  [C_0402]  149.66 62.58 270 bottom
PC755  -  [C_0402]  148.9 78.96 0 top
PC756  -  [C_0402]  150.55 58.14 270 bottom
PC757  -  [C_0402]  151.44 59.89 90 bottom
PC758  -  [C_0402]  151.45 62.57 180 top
PC759  -  [C_0402]  151.45 61.68 180 top
PC760  -  [C_0402]  150.54 61.68 0 bottom
PC761  -  [C_0402]  149.66 64.36 270 top
PC762  -  [C_0402]  149.66 58.11 90 bottom
PC763  -  [C_0402]  154.8 61.75 180 top
PC764  -  [C_0603]  140.87 69.5 0 top
PC765  -  [C_0603]  140.88 69.48 0 bottom
PC766  -  [C_0603]  140.9 71 0 bottom
PC767  -  [C_0603]  140.88 70.75 0 top
PC768  -  [C_0603]  127.57 71.41 270 bottom
PC769  -  [C_0603]  139.1 70.56 90 top
PC770  -  [C_0603]  136.56 70.56 90 top
PC771  -  [C_0603]  139.1 70.56 90 bottom
PC772  -  [C_0603]  108.85 78.57 270 top
PC773  -  [C_0603]  137.83 70.56 90 bottom
PC774  -  [C_0603]  136.56 70.56 90 bottom
PC775  -  [C_0603]  107.27 78.54 270 top
PC776  -  [C_0603]  102.57 77.42 0 top
PC777  -  [C_0603]  135.29 70.56 90 bottom
PC778  -  [C_0603]  126.14 67.19 180 bottom
PC779  -  [C_0603]  135.29 70.56 90 top
PC780  -  [C_0603]  137.83 70.56 90 top
PC781  -  [C_0402]  105.47 78.59 270 top
PC782  -  [C_D2]  145.45 71.04 270 top
PC783  -  [C_0603]  126.14 68.46 180 bottom
PC784  -  [C_0402]  111.08 78.57 270 top
PC785  -  [C_D2]  140.33 77.78 0 top
PC786  -  [C_D2]  145.77 87.54 0 bottom
PC787  -  [C_D2]  150.02 71.13 0 top
PD1  -  [RB715F_SOT323-3]  200.4 78.49 90 bottom
PD100  -  [RB715F_SOT323-3]  145.92 16.9 90 bottom
PF100  -  [F_1206]  43.21 99.7 0 bottom
PF101  -  [F_1206]  205.14 89.67 270 bottom
PH100  -  [R_0402]  118.07 77.63 0 top
PH701  -  [R_0402]  149.05 67.72 0 bottom
PH702  -  [R_0402]  149.82 84.68 180 bottom
PH703  -  [R_0402]  155.79 84.26 0 top
PH704  -  [R_0402]  153.41 77.23 0 top
PJ1  -  [JUMP_43X118]  101 55.16 270 top
PJ2  -  [JUMP_43X118]  108.74 55.17 270 top
PJ3  -  [JUMP_43X118]  186.35 22.04 270 top
PJ4  -  [JUMP_43X118]  186.74 28.9 90 top
PJ5  -  [JUMP_43X79]  52.99 70.37 90 top
PJ6  -  [JUMP_43X79]  53.88 64.42 270 top
PJ301  -  [JUMP_43X118]  204.18 37.97 0 bottom
PJ302  -  [JUMP_43X118]  44.56 34.12 270 bottom
PJ401  -  [JUMP_43X118]  140.76 38.23 180 bottom
PJ402  -  [JUMP_43X118]  140.76 32.96 180 bottom
PJ403  -  [JUMP_43X39]  151.39 38.3 90 bottom
PJ501  -  [JUMP_43X79]  59.15 67.01 90 top
PJ502  -  [JUMP_43X79]  62.82 56.27 90 top
PJ601  -  [JUMP_43X79]  71.95 76.52 180 top
PJ602  -  [JUMP_43X79]  70.85 72.71 0 top
PL100  -  [TAI-T_HCB2012KF-121T50_2P]  45.83 97.7 270 bottom
PL101  -  [TAI-T_HCB2012KF-121T50_2P]  47.6 97.7 270 bottom
PL102  -  [TAI-T_HCB2012KF-121T50_2P]  205.52 85.35 180 bottom
PL103  -  [TAI-T_HCB2012KF-121T50_2P]  205.52 83.57 180 bottom
PL200  -  [TAIYO_NRS4018T1R0NDGJ_2P]  184.43 71.26 0 top
PL201  -  [CYNTE_PCMB063T-4R7MS_2P]  189.53 68.94 90 bottom
PL301  -  [TAI-T_HCB2012KF-121T50_2P]  185.73 35.82 0 bottom
PL302  -  [CYNTE_PCMC063T-1R5MN_2P]  195.2 37.78 0 bottom
PL303  -  [TAI-T_HCB2012KF-121T50_2P]  41.56 51.95 270 bottom
PL304  -  [CYNTE_PCMC063T-1R5MN_2P]  44.5 43.09 270 bottom
PL401  -  [TAI-T_HCB2012KF-121T50_2P]  140.01 29.65 270 bottom
PL402  -  [L_7X7X3_M_2P]  145.61 35.63 270 bottom
PL403  -  [L_4X4X2_F_2P]  63.28 64.14 90 top
PL701  -  [TAI-T_HCB2012KF-121T50_2P]  164.55 80.32 0 top
PL702  -  [CYNTE_PDME064T-R36MS1R405_4P]  154.42 80.47 180 bottom
PL703  -  [CYNTE_PDME064T-R36MS1R405_4P]  154.46 72.26 180 bottom
PQ200  -  [2N7002KW_SOT323-3]  39.46 85.98 180 bottom
PQ201  -  [MDU1512RH_POWERDFN56-8-5]  47.15 88.15 180 bottom
PQ202  -  [AON7506_DFN33-8-5]  44.23 85.73 0 bottom
PQ203  -  [AO4466L_SO8]  189.88 74.43 90 top
PQ204  -  [SIS412DN-T1-GE3_POWERPAK8-5]  191.78 70.71 90 top
PQ205  -  [SIS412DN-T1-GE3_POWERPAK8-5]  189.1 66.14 0 top
PQ401  -  [AON7408L_DFN8-5]  144.08 29.28 90 top
PQ402  -  [AON7406L_DFN8-5]  145.61 28.39 0 top
PQ701  -  [AON7934_DFN3X3A8-10]  157.63 83.12 180 top
PQ702  -  [AON7934_DFN3X3A8-10]  155.68 74.15 0 top
PR102  -  [R_0402]  202.09 90.2 270 bottom
PR104  -  [R_0402]  203.1 90.2 270 bottom
PR105  -  [R_0402]  199.93 90.2 270 bottom
PR107  -  [R_0402]  200.95 90.2 270 bottom
PR109  -  [R_0402]  198.91 90.2 270 bottom
PR110  -  [R_0402]  82.45 18.95 270 top
PR111  -  [R_0402]  83.5 15.83 0 top
PR112  -  [R_0402]  84.08 14.92 270 top
PR113  -  [R_0402]  85.88 16.85 270 top
PR115  -  [R_0603]  148.94 17.92 0 bottom
PR116  -  [R_0603]  148.94 16.52 0 bottom
PR122  -  [R0402_0OHM]  155.23 55.38 90 top
PR123  -  [R_0402]  157.39 55.76 180 top
PR200  -  [R_0402]  39.86 89.76 180 bottom
PR201  -  [R_0402]  38.95 88.83 0 bottom
PR202  -  [R_1206_4P-D]  42.07 84.08 270 bottom
PR209  -  [R_0402]  39.53 84.72 270 bottom
PR210  -  [R_0603]  42.71 86.11 180 bottom
PR211  -  [R_0402]  38.51 84.72 270 bottom
PR212  -  [R_0402]  190.14 79.64 0 top
PR213  -  [R_0402]  190.14 79.64 0 bottom
PR214  -  [R_1206]  195.55 75.95 270 bottom
PR215  -  [R_0402]  202.23 76.53 180 bottom
PR216  -  [R_0402]  201.32 74.75 0 bottom
PR217  -  [R_0603]  193.58 72.02 90 top
PR218  -  [R0402_0OHM]  205.15 68.72 180 bottom
PR219  -  [R0402_0OHM]  205.15 67.83 180 bottom
PR220  -  [R_0603]  196.12 70.75 180 bottom
PR221  -  [R_1206_4P-D]  189.56 78.05 0 bottom
PR222  -  [R_0402]  198.74 66.37 180 bottom
PR223  -  [R_1206]  193.9 70.11 270 top
PR224  -  [R0402_0OHM]  205.15 69.6 180 bottom
PR225  -  [R_0402]  198.74 67.26 180 bottom
PR226  -  [R_0402]  199.61 67.27 270 bottom
PR227  -  [R_0402]  200.5 67.27 270 bottom
PR228  -  [R_0402]  199.55 72.26 90 top
PR229  -  [R_0402]  200.5 73.17 270 top
PR301  -  [R_0402]  187.83 42.86 180 bottom
PR302  -  [R_0402]  190.69 42.87 270 bottom
PR303  -  [R_0402]  188.84 42.86 0 bottom
PR304  -  [R_0603]  188.33 40.51 180 bottom
PR305  -  [R_1206]  197.61 33.27 180 bottom
PR306  -  [R_0402]  194.25 42.87 270 bottom
PR307  -  [R0402_0OHM]  195.14 42.87 270 bottom
PR308  -  [R_0402]  193.36 41.96 90 bottom
PR309  -  [R_0402]  48.77 44.22 180 bottom
PR310  -  [R_0603]  47.93 48.6 0 bottom
PR311  -  [R_1206]  39.99 40.41 90 bottom
PR312  -  [R_0402]  38.77 48.14 270 bottom
PR313  -  [R_0402]  37.75 46.11 270 bottom
PR314  -  [R_0402]  190.74 40.24 0 top
PR401  -  [R_0603]  149.8 29.6 90 bottom
PR402  -  [R_0402]  153.62 27.69 180 bottom
PR403  -  [R_1206]  149.42 31.25 270 top
PR404  -  [R_0603]  155.58 26.42 90 bottom
PR405  -  [R_0603]  155.58 26.42 90 top
PR406  -  [R_0402]  156.66 26.79 90 top
PR407  -  [R_0402]  155.59 34.55 180 bottom
PR408  -  [R_0402]  153.42 26.79 90 top
PR409  -  [R_0402]  155.58 35.43 90 bottom
PR410  -  [R0402_0OHM]  155.58 29.98 180 top
PR411  -  [R0402_0OHM]  155.58 33.03 180 top
PR501  -  [R0402_0OHM]  57.5 62.3 270 top
PR502  -  [R_0402]  59.2 58.35 0 top
PR503  -  [R_0402]  58.39 62.3 270 top
PR504  -  [R_0603]  62.96 62.42 0 top
PR505  -  [R_0402]  58.39 60.15 270 top
PR506  -  [R_0402]  59.28 59.23 90 top
PR601  -  [R_0402]  64.79 81.42 270 top
PR602  -  [R_0402]  67.46 81.42 270 top
PR603  -  [R_0402]  64.6 71.24 90 top
PR604  -  [R_0402]  66.57 80.51 90 top
PR605  -  [R_0402]  66.38 72.15 270 top
PR701  -  [R_0402]  161.13 57.22 90 bottom
PR702  -  [R_0402]  160.23 61.68 0 bottom
PR703  -  [R_0402]  160.23 59.01 0 bottom
PR704  -  [R_0402]  162.02 64.36 270 top
PR705  -  [R_0402]  162.02 59.89 90 bottom
PR706  -  [R_0402]  161.14 63.46 180 top
PR707  -  [R_0402]  160.23 62.57 0 bottom
PR708  -  [R_0603]  159.47 83.09 0 top
PR709  -  [R_0603]  161.27 64.53 180 bottom
PR710  -  [R_0402]  161.13 58.68 180 top
PR711  -  [R_0402]  161.14 60.79 180 top
PR712  -  [R_0402]  161.14 63.46 180 bottom
PR713  -  [R_1206]  149.42 83.68 270 top
PR714  -  [R_0603]  161.68 59.73 180 top
PR715  -  [R_0402]  155.84 60.9 270 top
PR716  -  [R_0402]  158.97 57.22 90 bottom
PR717  -  [R0402_0OHM]  158.08 57.22 90 bottom
PR718  -  [R0402_0OHM]  156.3 66.45 90 bottom
PR719  -  [R_0402]  155.41 67.36 270 bottom
PR720  -  [R_0402]  156.78 57.22 90 bottom
PR721  -  [R_0402]  155.89 57.22 90 bottom
PR722  -  [R0402_0OHM]  152.33 57.22 90 bottom
PR723  -  [R_0402]  154.11 58.14 270 bottom
PR724  -  [R_0402]  154.11 58.12 0 top
PR725  -  [R_0402]  155.89 57.22 90 top
PR726  -  [R_0402]  156.78 57.22 90 top
PR727  -  [R_0402]  153.22 57.22 90 bottom
PR728  -  [R_0603]  154.31 73.99 90 top
PR729  -  [R_0402]  151.45 63.46 180 bottom
PR730  -  [R_0603]  151.25 65.81 270 bottom
PR731  -  [R_1206]  149.4 75.13 90 top
PR732  -  [R_0402]  150.54 62.57 0 bottom
PR733  -  [R_0402]  149.66 60.8 270 bottom
PR734  -  [R_0402]  151.46 58.67 180 top
PR735  -  [R_0603]  150 59.72 0 top
PR736  -  [R_0402]  151.44 57.22 90 bottom
PR737  -  [R_0402]  151.45 64.35 180 top
PR738  -  [R_0402]  151.45 63.46 180 top
PR739  -  [R_0402]  151.45 60.79 180 top
PR740  -  [R_0402]  150.54 59.01 0 bottom
PR741  -  [R_0402]  150.55 59.89 90 bottom
PU1  -  [BQ24780RUYR_WQFN28_4X4]  199.18 73.03 270 bottom
PU301  -  [SYX196BQNC_QFN10_3X3]  192.26 40.21 180 bottom
PU302  -  [SYX196CQNC_QFN10_3X3]  46.36 45.95 90 bottom
PU303  -  [RT8207PGQW_WQFN20_3X3]  152.87 33 0 bottom
PU501  -  [SY8003DFC_DFN8_2X2]  60.44 59.67 0 top
PU601  -  [APL5930KAI-TRG_SO8]  65.11 73.73 0 top
PU602  -  [ISL95833HRTZ-T_TQFN32_4X4]  157.25 60.03 180 bottom
Q2  -  [2N7002K_SOT23-3]  163.47 46.22 270 top
Q3  -  [2N7002K_SOT23-3]  159.37 41.41 270 top
Q4  -  [2N7002K_SOT23-3]  152.34 48.66 180 top
Q5  -  [2N7002K_SOT23-3]  158.82 47.14 180 top
QB1  -  [2N7002K_SOT23-3]  67.93 6.08 180 bottom
QC1  -  [MESS138W-G_SOT323-3]  123.98 71.25 270 bottom
QC2  -  [MESS138W-G_SOT323-3]  89.82 28.28 270 top
QC3  -  [MESS138W-G_SOT323-3]  85.81 76.54 180 top
QC4  -  [MESS138W-G_SOT323-3]  137.19 83.95 270 top
QC5  -  [MESS138W-G_SOT323-3]  133.64 83.95 270 top
QM1  -  [AO5804EL_SC89-6]  171.23 87.77 0 bottom
QX1  -  [2N7002K_SOT23-3]  50.61 90.56 90 bottom
QX2  -  [PMV65XP_SOT23-3]  54.14 86.11 270 bottom
QY1  -  [DMN66D0LDW-7_SOT363-6]  14.95 94.84 0 top
QY2  -  [MESS138W-G_SOT323-3]  19.51 93.65 90 top
QY3  -  [MESS138W-G_SOT323-3]  19.51 91.27 90 top
R1  -  [R0402_0OHM]  220.31 92.71 180 top
R2  -  [R_0402]  220.31 93.62 180 top
R3  -  [R_0402]  28.76 91.36 270 top
R6  -  [R_0402]  15.15 5.47 90 top
R7  -  [R_0402]  21.49 5.47 90 top
R12  -  [R_0402]  23.55 6.36 270 top
R13  -  [R_0402]  22.51 5.47 90 top
R14  -  [R_0402]  30.39 5.47 90 top
R15  -  [R0402_0OHM]  24.54 6.36 270 top
R16  -  [R_0402]  10.19 11.54 0 top
RA1  -  [R0603_0OHM]  32.23 29.85 180 top
RA2  -  [R0603_0OHM]  23.83 30.15 90 top
RA3  -  [R0603_0OHM]  31.85 25.24 180 top
RA4  -  [R0603_0OHM]  17.48 16.56 270 top
RA5  -  [R0603_0OHM]  31.66 21.85 0 top
RA6  -  [R_0402]  18.45 25.66 0 top
RA7  -  [R_0402]  18.45 24.77 0 top
RA8  -  [R0402_0OHM]  16.42 21.09 270 bottom
RA9  -  [R0402_0OHM]  13.75 21.09 270 bottom
RA10  -  [R_0402]  33.01 28.46 180 top
RA11  -  [R_0402]  27.15 32.59 90 top
RA12  -  [R0402_0OHM]  31.08 28.48 180 top
RA13  -  [R_0402]  128.51 76.34 90 bottom
RA14  -  [R_0402]  18.7 17.36 45 top
RA15  -  [R_0402]  13.75 22.89 90 top
RA16  -  [R_0402]  13.75 21.98 270 top
RA17  -  [R_0603]  19.34 23.63 180 top
RA18  -  [R_0603]  19.34 26.81 180 top
RA19  -  [R_0402]  27.05 18.51 270 top
RA20  -  [R_0402]  27.16 18.04 270 bottom
RA21  -  [R0402_0OHM]  15.65 26.68 270 top
RA22  -  [R_0402]  27.19 15.76 90 top
RA23  -  [R_0402]  28.48 15.76 90 top
RA24  -  [R0402_0OHM]  13.11 12.38 90 top
RA25  -  [R_0402]  26.07 18.68 270 top
RA26  -  [R0402_0OHM]  30.01 14.15 90 top
RA27  -  [R_0402]  24.47 18.95 90 top
RA28  -  [R0402_0OHM]  32.88 19.19 180 top
RA29  -  [R_0402]  26.25 17.13 90 bottom
RA30  -  [R_0402]  21.96 30.36 180 bottom
RA31  -  [R_0402]  22.89 29.77 90 bottom
RA32  -  [R_0402]  19.46 21.65 90 top
RB1  -  [R_0402]  78.14 31.57 270 top
RB2  -  [R_0603]  68.93 32.04 270 top
RB3  -  [R_0402]  77.25 31.58 270 top
RB4  -  [R0603_0OHM]  82.07 9.68 180 top
RB5  -  [R_0402]  82.5 21.21 0 top
RB6  -  [R_0402]  82.6 27.73 0 top
RB7  -  [R0402_0OHM]  82.6 28.62 0 top
RB8  -  [R_0402]  74.96 8.72 270 top
RB9  -  [R_0402]  75.85 8.72 270 top
RB10  -  [R_0402]  61.75 25.7 90 top
RB11  -  [R_0402]  75.91 31.57 270 top
RB12  -  [R_0402]  72.8 7.63 270 top
RB13  -  [R_0402]  75.03 31.58 270 top
RB14  -  [R_0402]  73.82 6.61 270 top
RB15  -  [R_0402]  75.73 6.61 270 top
RB16  -  [R_0402]  71.33 9.91 270 top
RB17  -  [R_0402]  72.3 9.91 270 top
RB18  -  [R_0402]  70.01 31.58 270 top
RB20  -  [R_0402]  83.47 18.06 90 top
RB21  -  [R_0402]  83.06 14.92 270 top
RB22  -  [R0402_0OHM]  83.42 24.74 180 top
RB23  -  [R_0402]  84.33 22.66 0 top
RB24  -  [R0402_0OHM]  82.58 16.08 90 top
RB25  -  [R_0402]  83.42 23.58 180 top
RB26  -  [R0402_0OHM]  84.43 16.92 180 top
RB27  -  [R_0402]  71.29 31.62 270 top
RB29  -  [R_0402]  72.24 31.63 270 top
RB30  -  [R_0402]  72.8 33.41 270 top
RB31  -  [R_0402]  64.34 8.75 0 bottom
RB32  -  [R_0402]  82.53 22.68 0 top
RC1  -  [R_0402]  111.21 71.98 270 top
RC2  -  [R_0402]  112.09 71.98 270 top
RC3  -  [R_0402]  108.55 71.16 0 top
RC4  -  [R_0402]  113.85 71.1 180 top
RC5  -  [R_0402]  110.32 71.97 270 top
RC6  -  [R_0402]  117.89 61.48 90 bottom
RC7  -  [R_0402]  117 61.48 90 bottom
RC8  -  [R_0402]  53.7 78.62 180 bottom
RC9  -  [R_0402]  102.59 74.44 270 top
RC10  -  [R0402_0OHM]  58.83 79.96 270 bottom
RC11  -  [R_0402]  113.89 95.13 180 top
RC12  -  [R_0402]  61.46 77.72 180 bottom
RC13  -  [R0402_0OHM]  63.28 79.32 270 bottom
RC14  -  [R_0402]  91.47 74.92 90 bottom
RC15  -  [R_0402]  92.55 75.83 270 bottom
RC16  -  [R_0402]  115.16 81.66 0 top
RC17  -  [R_0402]  128.4 89.26 180 bottom
RC18  -  [R_0402]  114.89 83.22 180 top
RC19  -  [R_0402]  124.69 79.6 0 bottom
RC20  -  [R_0402]  93 79.64 0 bottom
RC21  -  [R_0402]  121.42 76.46 180 top
RC22  -  [R_0402]  125.51 73.79 180 bottom
RC23  -  [R0402_0OHM]  125.51 72.9 180 bottom
RC24  -  [R_0402]  111.94 93.05 180 bottom
RC25  -  [R_0402]  163.61 90.43 90 top
RC26  -  [R_0402]  87.79 80.02 90 top
RC27  -  [R_0402]  84.11 77.48 90 top
RC28  -  [R_0402]  121.21 73.76 90 top
RC29  -  [R_0402]  119.37 74.53 0 top
RC30  -  [R_0402]  107.3 82.94 0 top
RC31  -  [R_0402]  107.3 83.8 0 top
RC32  -  [R_0402]  119.32 73.46 180 top
RC33  -  [R_0402]  121.4 75.54 180 top
RC34  -  [R_0402]  116.67 73.59 0 top
RC35  -  [R_0402]  91.79 85.48 0 bottom
RC36  -  [R_0402]  89.49 85.48 0 bottom
RC37  -  [R_0402]  84.49 83.7 270 top
RC38  -  [R_0402]  88.6 84.59 90 bottom
RC39  -  [R_0402]  87.9 78.57 0 bottom
RC40  -  [R_0402]  90.71 78.62 180 bottom
RC41  -  [R_0402]  93.28 78.7 180 bottom
RC42  -  [R_0402]  93.76 90.81 270 bottom
RC43  -  [R_0402]  90.58 94.5 270 bottom
RC44  -  [R_0402]  103.26 79.46 315 top
RC45  -  [R_0402]  98.33 80.71 90 top
RC46  -  [R_0402]  99.88 81.03 0 top
RC47  -  [R_0402]  91.92 87.65 90 bottom
RC48  -  [R0402_0OHM]  81.03 81.54 180 top
RC49  -  [R_0402]  92.88 87.65 270 bottom
RC50  -  [R_0402]  57.67 45.35 180 top
RC51  -  [R_0402]  57.31 40.27 180 top
RC52  -  [R_0402]  54.77 48.27 180 top
RC53  -  [R_0402]  52.55 36.02 270 top
RC54  -  [R_0402]  90.13 88.57 270 bottom
RC55  -  [R_0402]  104.3 95.18 90 top
RC56  -  [R_0402]  98.28 82.53 90 top
RC57  -  [R_0402]  99.17 82.53 90 top
RC58  -  [R_0402]  126.02 96.02 270 top
RC59  -  [R_0402]  90.49 84 180 bottom
RC60  -  [R_0402]  95.44 95.07 0 top
RC61  -  [R_0402]  91.91 84 0 bottom
RC62  -  [R_0402]  105.19 96.09 270 top
RC63  -  [R_0402]  127.03 95.13 90 top
RC64  -  [R_0402]  96.93 94.62 270 bottom
RC65  -  [R_0402]  121.14 83.27 180 top
RC66  -  [R_0402]  128.3 83.19 180 bottom
RC67  -  [R_0402]  128.21 84.18 180 bottom
RC68  -  [R_0402]  124.8 82.3 0 bottom
RC69  -  [R_0402]  121.62 60.44 180 bottom
RC70  -  [R0402_0OHM]  119.79 93.61 90 bottom
RC71  -  [R_0402]  121.06 81.67 180 top
RC72  -  [R_0402]  105.11 76.66 225 top
RC73  -  [R_0402]  101.26 76.24 90 top
RC74  -  [R0402_0OHM]  125.63 89.79 180 bottom
RC75  -  [R0402_0OHM]  106.71 75.57 180 top
RC76  -  [R0603_0OHM]  101.25 95.19 90 top
RC77  -  [R0603_0OHM]  119.8 80.62 0 top
RC78  -  [R_0402]  124.68 75.7 0 bottom
RC79  -  [R_0402]  124.67 74.81 0 bottom
RC80  -  [R0402_0OHM]  102.57 94.09 270 bottom
RC81  -  [R_0402]  117.96 72.55 0 top
RC82  -  [R_0402]  127.41 82.17 0 bottom
RC83  -  [R_0402]  89.23 87.64 270 bottom
RC84  -  [R_0402]  89.24 88.56 180 bottom
RD1  -  [R_0402]  69.15 48.18 180 top
RD2  -  [R_0402]  69.13 46.33 180 top
RD3  -  [R_0402]  107.73 38.11 180 top
RD4  -  [R_0402]  107.73 37.09 180 top
RD5  -  [R0402_0OHM]  127.82 45.95 90 top
RD6  -  [R0402_0OHM]  129.63 46.87 270 top
RL1  -  [R0603_0OHM]  31.77 62.81 90 bottom
RL2  -  [R_0402]  41.03 68.5 180 bottom
RL3  -  [R_0402]  40.14 69.51 0 bottom
RL4  -  [R_0402]  38.72 64.16 270 bottom
RL5  -  [R0402_0OHM]  16.8 79 270 bottom
RL6  -  [R_0402]  34.31 63.32 90 bottom
RL7  -  [R0402_0OHM]  15.91 79 270 bottom
RL8  -  [R_0805]  17.94 68.97 90 top
RM1  -  [R0805_0OHM]  173.26 87.64 90 top
RM2  -  [R_0402]  175.93 88.43 90 bottom
RM3  -  [R_0402]  174.33 88.47 90 bottom
RM4  -  [R0402_0OHM]  169.2 88.4 0 bottom
RM5  -  [R0402_0OHM]  164.88 91.32 270 top
RM6  -  [R0402_0OHM]  162.34 91.32 270 top
RM11  -  [R_0402]  151.06 91.73 270 top
RM12  -  [R_0402]  150.17 91.73 270 top
RM13  -  [R_0402]  151.95 90.81 90 top
RM14  -  [R_0402]  155.96 91.47 270 top
RM15  -  [R_0402]  154.68 91.48 270 top
RM16  -  [R_0402]  160.9 88.57 0 top
RM17  -  [R_0402]  160.9 89.45 0 top
RM18  -  [R_0402]  171.74 88.78 0 bottom
RM19  -  [R_0402]  170.21 86.11 270 bottom
RM20  -  [R_0402]  171.23 85.1 0 bottom
RM21  -  [R_0402]  149.28 91.73 270 top
RO1  -  [R0805_0OHM]  222.15 103.64 90 top
RO2  -  [R0805_0OHM]  209.63 40.39 90 top
RO4  -  [R0805_0OHM]  208.44 51.19 90 top
RO5  -  [R_0402]  225.84 103.38 90 top
RPB1  -  [RP_0804_8P4R]  70.21 6.26 90 top
RPC1  -  [RP_0804_8P4R]  78.64 76.59 0 top
RPC2  -  [RP_0804_8P4R]  57.08 82.3 0 bottom
RPC3  -  [RP_0804_8P4R]  123.35 95.38 90 top
RPC4  -  [RP_0804_8P4R]  126.26 78.37 180 bottom
RPC5  -  [RP_0804_8P4R]  99.78 76.51 270 top
RPC6  -  [RP_0804_8P4R]  86.14 83.83 0 top
RPC7  -  [RP_0804_8P4R]  88.96 81.42 0 bottom
RPC8  -  [RP_0804_8P4R]  56.8 43.44 0 top
RPC9  -  [RP_0804_8P4R]  126.52 86.24 0 bottom
RPY1  -  [RP_0804_8P4R]  17.05 89.59 270 bottom
RQ1  -  [R_0402]  191.82 25.59 0 top
RQ2  -  [R_0402]  192.71 27.63 180 top
RQ3  -  [R_0402]  49.15 67.79 180 top
RQ4  -  [R_0402]  49.18 64.91 180 top
RQ5  -  [R_0402]  161.4 46.04 90 top
RQ6  -  [R_0603]  155.81 40.77 0 top
RQ7  -  [R_0603]  154.67 49.58 90 top
RQ8  -  [R_0402]  165.48 43.72 270 top
RQ9  -  [R_0402]  156.15 47.64 270 top
RR1  -  [R_0402]  42.33 13.33 0 top
RR2  -  [R0402_0OHM]  44.89 9.25 270 top
RR3  -  [R0402_0OHM]  45.89 9.25 270 top
RR4  -  [R_0402]  46.88 8.34 90 top
RR5  -  [R0402_0OHM]  48.88 9.23 270 top
RR6  -  [R0402_0OHM]  49.88 9.25 270 top
RR7  -  [R0402_0OHM]  50.88 9.25 270 top
RR8  -  [R_0402]  51.64 11.57 0 top
RS1  -  [R_0402]  23.42 45.62 0 bottom
RS2  -  [R_0402]  15.27 41.28 90 bottom
RS3  -  [R_0402]  23.42 44.73 0 bottom
RS4  -  [R_0402]  20.38 35.87 0 bottom
RS5  -  [R_0402]  20.38 34.85 0 bottom
RS6  -  [R0402_0OHM]  22.73 50.1 0 bottom
RS7  -  [R0402_0OHM]  22.73 49.21 0 bottom
RS8  -  [R0402_0OHM]  22.7 48.33 0 bottom
RS9  -  [R0402_0OHM]  22.7 47.44 0 bottom
RS10  -  [R_0402]  202.73 57.29 180 top
RS11  -  [R_0402]  190.28 60.64 180 top
RS12  -  [R_0402]  189.39 57.98 0 top
RS13  -  [R_0402]  189.59 55.28 0 top
RS14  -  [R_0402]  189.39 57.09 0 top
RS15  -  [R_0603]  192.44 53.22 0 top
RS16  -  [R_0402]  189.39 58.86 0 top
RS17  -  [R_0402]  189.39 59.75 0 top
RS18  -  [R_0402]  187.1 58.74 0 top
RS19  -  [R_0402]  187.1 59.91 0 top
RS20  -  [R_0402]  187.1 55 90 top
RW1  -  [R_0402]  90.71 19.25 270 top
RW2  -  [R_0402]  90.38 24.77 180 top
RW3  -  [R_0402]  92.29 17.13 0 top
RW4  -  [R_0402]  92.3 18.14 0 top
RW5  -  [R_0402]  101.6 16.87 180 top
RW6  -  [R_0402]  92.29 16.11 0 top
RW7  -  [R_0402]  94.52 18.17 0 top
RW8  -  [R_0402]  94.52 17.15 0 top
RW9  -  [R_0402]  94.52 16.13 0 top
RX1  -  [R0402_0OHM]  75.6 85.98 270 top
RX2  -  [R_0402]  57.74 88.38 90 bottom
RX3  -  [R_0402]  49.84 88.09 90 bottom
RX4  -  [R_0402]  59.01 89.27 270 bottom
RX5  -  [R_0402]  52.03 92.97 0 bottom
